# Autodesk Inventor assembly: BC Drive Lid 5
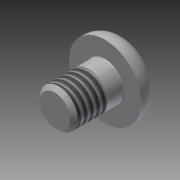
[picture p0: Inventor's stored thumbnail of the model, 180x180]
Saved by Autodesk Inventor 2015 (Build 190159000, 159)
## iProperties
Created: 2007-02
Part Number: BC Drive Lid 5
Document SubType Name: Assembly
Designer: Autodesk, Inc.
Mass: 1.89148 g
Surface Area: 2.92112 cm^2
Volume: 0.240646 cm^3
Density: 7.86 g/cm^3
ClientObjectVersion: 1
Author: Autodesk, Inc.
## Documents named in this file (2)
- C:\Users\Public\Documents\Autodesk\Inventor 2015\Samples\Models\Assemblies\Blower\Blower\Design Accelerator\BC Drive Lid 41.iam
- C:\Users\Public\Documents\Autodesk\Inventor 2015\Samples\Standard Parts\en-US\ANSI B18.3(03)\ANSI B18.3 - 10-32 UNF - UNF - 0.25(1).ipt
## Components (1 placed, 1 different names)
1. ANSI B18.3 - No. 10-32 - 1/4:1
